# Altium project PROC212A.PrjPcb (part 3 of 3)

## Sheet PROC212A_DCA1000_LP_BP_Connectors.SchDoc: DCA1000_LP_BP_CONN
size 431 x 279 mm; Date: Not shown in title block; ApprovedBy: Not shown in title block; CheckedBy: Not shown in title block; Author: Not shown in title block; CompanyName: Not shown in title block; DrawnBy: Mistral; Engineer: Not shown in title block; Organization: Not shown in title block; Address1: Not shown in title block; Address2: Not shown in title block; Address3: Not shown in title block; Address4: Not shown in title block; DocumentNumber: 14; Revision: Use project parameter SCH_Rev; SheetNumber: 14; SheetTotal: 15; PageSetup: Record=PageOptions¦CenterHorizontal=True¦CenterVertical=True¦PrintScale=1.00¦XCorrection=1.00¦YCorrection=1.00¦PrintKind=0¦BorderSize=5000000¦LeftOffset=0¦BottomOffset=0¦Orientation=2¦PaperLength=1000¦PaperWidth=1000¦Scale=100¦PaperSource=15¦PrintQuality=600¦MediaType=1¦DitherType=10¦PaperKind=Letter¦PrintScaleMode=1
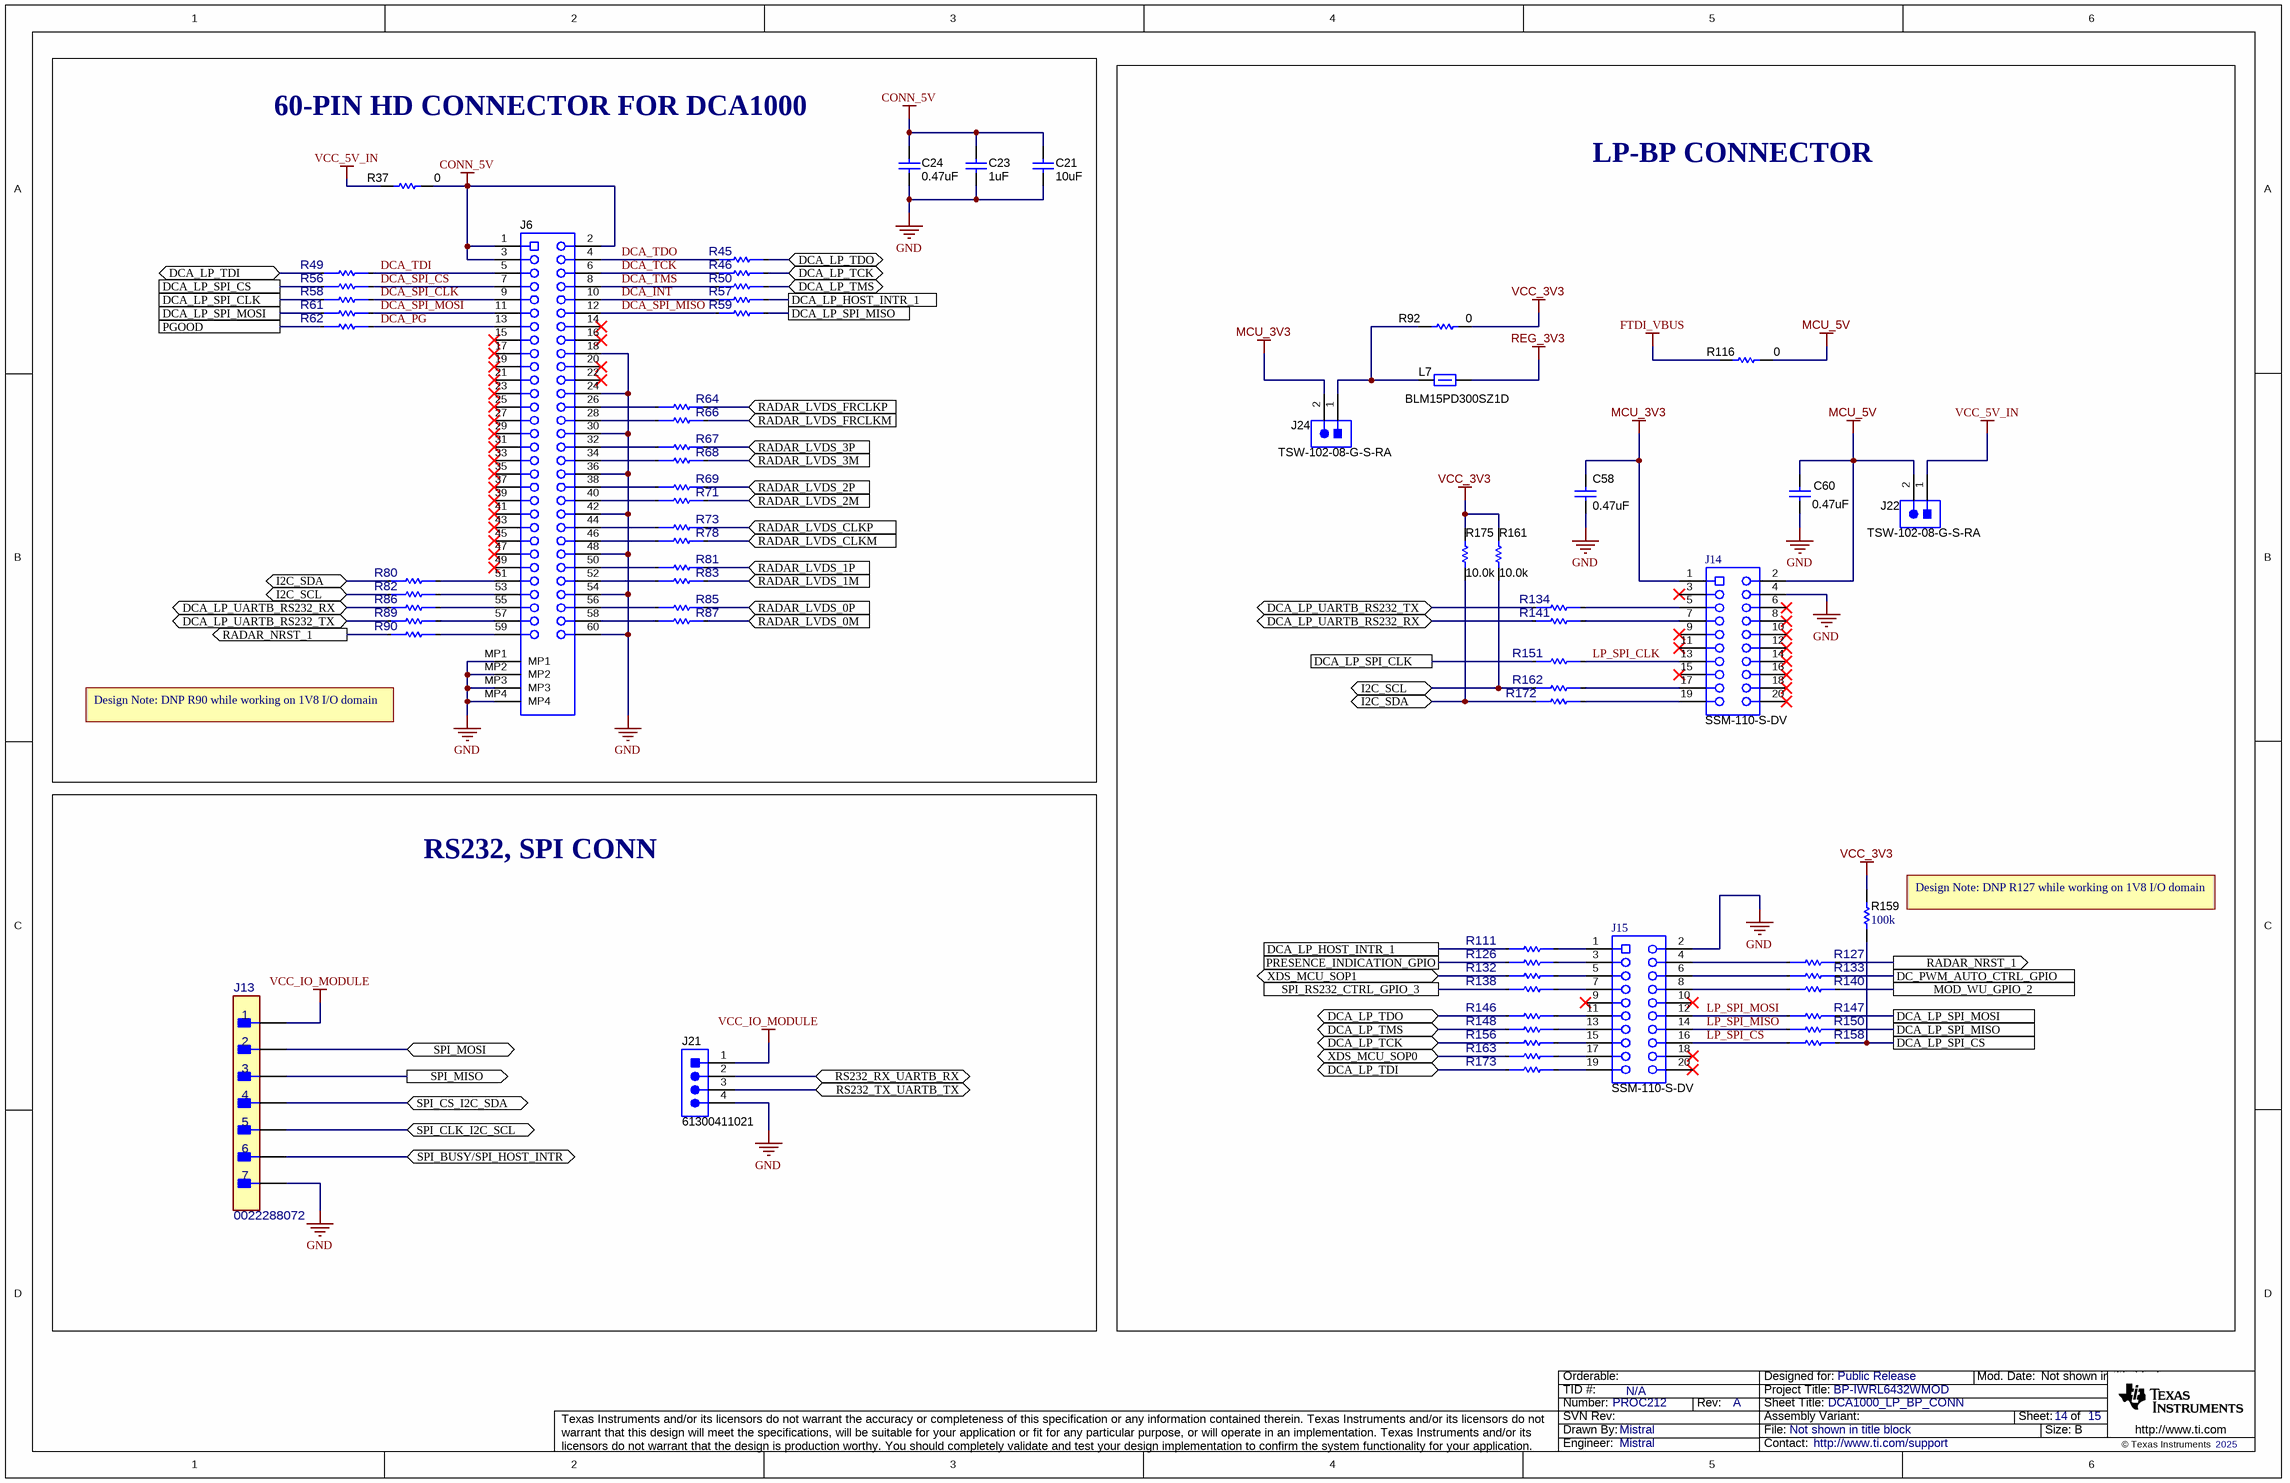
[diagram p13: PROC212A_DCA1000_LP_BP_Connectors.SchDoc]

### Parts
C21  ValueDisplayed: 10uF  [0603S]  (hidden comment: GRT188R61A106KE13D)
C23  ValueDisplayed: 1uF  [0402L]  (hidden comment: GRT155C81A105KE01D)
C24  ValueDisplayed: 0.47uF  [0402L]  (hidden comment: GCM155C71A474KE36D)
C58  ValueDisplayed: 0.47uF  [0402L]  (hidden comment: GCM155C71A474KE36D)
C60  ValueDisplayed: 0.47uF  [0402L]  (hidden comment: GCM155C71A474KE36D)
J6  QSH-030-01-L-D-A  [Samtec_QSH-030-01-X-D-A]  (value not drawn)
J13  0022288072  [FP-0022288072_HDR7-MFG]
J14  SSM-110-S-DV  [Samtec_SSM-110-x-DV]
J15  SSM-110-S-DV  [Samtec_SSM-110-x-DV]
J21  61300411021  [Wurth_61300411021]
J22  TSW-102-08-G-S-RA  [TSW-102-08-G-S-RA]
J24  TSW-102-08-G-S-RA  [TSW-102-08-G-S-RA]
L7  BLM15PD300SZ1D  [0402L]
R37  ValueDisplayed: 0  [0603]  (hidden comment: MCT06030Z0000ZP500)
R45  ERJ-2GE0R00X  [FP-ERJ-2GE0R00X_0402-MFG]  (value not drawn)
R46  ERJ-2GE0R00X  [FP-ERJ-2GE0R00X_0402-MFG]  (value not drawn)
R49  ERJ-2GE0R00X  [FP-ERJ-2GE0R00X_0402-MFG]  (value not drawn)
R50  ERJ-2GE0R00X  [FP-ERJ-2GE0R00X_0402-MFG]  (value not drawn)
R56  ERJ-2GE0R00X  [FP-ERJ-2GE0R00X_0402-MFG]  (value not drawn)
R57  ERJ-2GE0R00X  [FP-ERJ-2GE0R00X_0402-MFG]  (value not drawn)
R58  ERJ-2GE0R00X  [FP-ERJ-2GE0R00X_0402-MFG]  (value not drawn)
R59  ERJ-2GE0R00X  [FP-ERJ-2GE0R00X_0402-MFG]  (value not drawn)
R61  ERJ-2GE0R00X  [FP-ERJ-2GE0R00X_0402-MFG]  (value not drawn)
R62  ERJ-2GE0R00X  [FP-ERJ-2GE0R00X_0402-MFG]  (value not drawn)
R64  ERJ-2GE0R00X  [FP-ERJ-2GE0R00X_0402-MFG]  (value not drawn)
R66  ERJ-2GE0R00X  [FP-ERJ-2GE0R00X_0402-MFG]  (value not drawn)
R67  ERJ-2GE0R00X  [FP-ERJ-2GE0R00X_0402-MFG]  (value not drawn)
R68  ERJ-2GE0R00X  [FP-ERJ-2GE0R00X_0402-MFG]  (value not drawn)
R69  ERJ-2GE0R00X  [FP-ERJ-2GE0R00X_0402-MFG]  (value not drawn)
R71  ERJ-2GE0R00X  [FP-ERJ-2GE0R00X_0402-MFG]  (value not drawn)
R73  ERJ-2GE0R00X  [FP-ERJ-2GE0R00X_0402-MFG]  (value not drawn)
R78  ERJ-2GE0R00X  [FP-ERJ-2GE0R00X_0402-MFG]  (value not drawn)
R80  ERJ-2GE0R00X  [FP-ERJ-2GE0R00X_0402-MFG]  (value not drawn)
R81  ERJ-2GE0R00X  [FP-ERJ-2GE0R00X_0402-MFG]  (value not drawn)
R82  ERJ-2GE0R00X  [FP-ERJ-2GE0R00X_0402-MFG]  (value not drawn)
R83  ERJ-2GE0R00X  [FP-ERJ-2GE0R00X_0402-MFG]  (value not drawn)
R85  ERJ-2GE0R00X  [FP-ERJ-2GE0R00X_0402-MFG]  (value not drawn)
R86  ERJ-2GE0R00X  [FP-ERJ-2GE0R00X_0402-MFG]  (value not drawn)
R87  ERJ-2GE0R00X  [FP-ERJ-2GE0R00X_0402-MFG]  (value not drawn)
R89  ERJ-2GE0R00X  [FP-ERJ-2GE0R00X_0402-MFG]  (value not drawn)
R90  ERJ-2GE0R00X  [FP-ERJ-2GE0R00X_0402-MFG]  (value not drawn)
R92  ValueDisplayed: 0  [0603]  (hidden comment: MCT06030Z0000ZP500)
R111  ERJ-2GE0R00X  [FP-ERJ-2GE0R00X_0402-MFG]  (value not drawn)
R116  ValueDisplayed: 0  [0603]  (hidden comment: MCT06030Z0000ZP500)
R126  ERJ-2GE0R00X  [FP-ERJ-2GE0R00X_0402-MFG]  (value not drawn)
R127  ERJ-2GE0R00X  [FP-ERJ-2GE0R00X_0402-MFG]  (value not drawn)
R132  ERJ-2GE0R00X  [FP-ERJ-2GE0R00X_0402-MFG]  (value not drawn)
R133  ERJ-2GE0R00X  [FP-ERJ-2GE0R00X_0402-MFG]  (value not drawn)
R134  ERJ-2GE0R00X  [FP-ERJ-2GE0R00X_0402-MFG]  (value not drawn)
R138  ERJ-2GE0R00X  [FP-ERJ-2GE0R00X_0402-MFG]  (value not drawn)
R140  ERJ-2GE0R00X  [FP-ERJ-2GE0R00X_0402-MFG]  (value not drawn)
R141  ERJ-2GE0R00X  [FP-ERJ-2GE0R00X_0402-MFG]  (value not drawn)
R146  ERJ-2GE0R00X  [FP-ERJ-2GE0R00X_0402-MFG]  (value not drawn)
R147  ERJ-2GE0R00X  [FP-ERJ-2GE0R00X_0402-MFG]  (value not drawn)
R148  ERJ-2GE0R00X  [FP-ERJ-2GE0R00X_0402-MFG]  (value not drawn)
R150  ERJ-2GE0R00X  [FP-ERJ-2GE0R00X_0402-MFG]  (value not drawn)
R151  ERJ-2GE0R00X  [FP-ERJ-2GE0R00X_0402-MFG]  (value not drawn)
R156  ERJ-2GE0R00X  [FP-ERJ-2GE0R00X_0402-MFG]  (value not drawn)
R158  ERJ-2GE0R00X  [FP-ERJ-2GE0R00X_0402-MFG]  (value not drawn)
R159  ValueDisplayed: 100k  [0402L]  (hidden comment: CRCW0402100KFKED)
R161  ValueDisplayed: 10.0k  [0402L]  (hidden comment: CRCW040210K0FKED)
R162  ERJ-2GE0R00X  [FP-ERJ-2GE0R00X_0402-MFG]  (value not drawn)
R163  ERJ-2GE0R00X  [FP-ERJ-2GE0R00X_0402-MFG]  (value not drawn)
R172  ERJ-2GE0R00X  [FP-ERJ-2GE0R00X_0402-MFG]  (value not drawn)
R173  ERJ-2GE0R00X  [FP-ERJ-2GE0R00X_0402-MFG]  (value not drawn)
R175  ValueDisplayed: 10.0k  [0402L]  (hidden comment: CRCW040210K0FKED)

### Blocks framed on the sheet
60-PIN HD CONNECTOR FOR DCA1000: C21 C23 C24 J6 R37 R45 R46 R49 R50 R56-R59 R61 R62 R64 R66-R69 R71 R73 R78 R80-R83 R85-R87 R89 R90
LP-BP CONNECTOR: C58 C60 J14 J15 J22 J24 L7 R92 R111 R116 R126 R127 R132-R134 R138 R140 R141 R146-R148 R150 R151 R156 R158 R159 R161-R163 R172 R173 R175
RS232, SPI CONN: J13 J21

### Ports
DC_PWM_AUTO_CTRL_GPIO, DCA_LP_HOST_INTR_1, DCA_LP_SPI_CLK, DCA_LP_SPI_CS, DCA_LP_SPI_MISO, DCA_LP_SPI_MOSI, DCA_LP_TCK (bidir), DCA_LP_TDI (bidir), DCA_LP_TDO (bidir), DCA_LP_TMS (bidir), DCA_LP_UARTB_RS232_RX (bidir), DCA_LP_UARTB_RS232_TX (bidir), I2C_SCL (bidir), I2C_SDA (bidir), MOD_WU_GPIO_2, PGOOD, PRESENCE_INDICATION_GPIO, RADAR_LVDS_0M (in), RADAR_LVDS_0P (in), RADAR_LVDS_1M (in), RADAR_LVDS_1P (in), RADAR_LVDS_2M (in), RADAR_LVDS_2P (in), RADAR_LVDS_3M (in), RADAR_LVDS_3P (in), RADAR_LVDS_CLKM (in), RADAR_LVDS_CLKP (in), RADAR_LVDS_FRCLKM (in), RADAR_LVDS_FRCLKP (in), RADAR_NRST_1 (out), RS232_RX_UARTB_RX (bidir), RS232_TX_UARTB_TX (bidir), SPI_BUSY/SPI_HOST_INTR (bidir), SPI_CLK_I2C_SCL (bidir), SPI_CS_I2C_SDA (bidir), SPI_MISO (out), SPI_MOSI (bidir), SPI_RS232_CTRL_GPIO_3, XDS_MCU_SOP0 (bidir), XDS_MCU_SOP1 (bidir)

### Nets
CONN_5V: C21.2 C23.1 C24.1 J6.1 J6.2 J6.3 R37.2
FTDI_VBUS: R116.1
GND: C21.1 C23.2 C24.2 C58.2 C60.2 J6.18 J6.24 J6.30 J6.36 J6.42 J6.48 J6.54 J6.60 J6.MP1 J6.MP2 J6.MP3 J6.MP4 J13.7 J14.4 J15.2 J21.4
MCU_3V3: C58.1 J14.1 J24.2
MCU_5V: C60.1 J14.2 J22.2 R116.2
REG_3V3: L7.2
VCC_3V3: R92.2 R159.2 R161.2 R175.2
VCC_5V_IN: J22.1 R37.1
VCC_IO_MODULE: J13.1 J21.1
DC_PWM_AUTO_CTRL_GPIO: R133.2 ; port DC_PWM_AUTO_CTRL_GPIO
DCA_INT: J6.10 R57.1
DCA_LP_HOST_INTR_1: R57.2 R111.1 ; port DCA_LP_HOST_INTR_1
DCA_LP_SPI_CLK: R58.1 R151.1 ; port DCA_LP_SPI_CLK
DCA_LP_SPI_CS: R56.1 R158.2 R159.1 ; port DCA_LP_SPI_CS
DCA_LP_SPI_MISO: R59.2 R150.2 ; port DCA_LP_SPI_MISO
DCA_LP_SPI_MOSI: R61.1 R147.2 ; port DCA_LP_SPI_MOSI
DCA_LP_TCK: R46.2 R156.1 ; port DCA_LP_TCK
DCA_LP_TDI: R49.1 R173.1 ; port DCA_LP_TDI
DCA_LP_TDO: R45.2 R146.1 ; port DCA_LP_TDO
DCA_LP_TMS: R50.2 R148.1 ; port DCA_LP_TMS
DCA_LP_UARTB_RS232_RX: R86.1 R141.1 ; port DCA_LP_UARTB_RS232_RX
DCA_LP_UARTB_RS232_TX: R89.1 R134.1 ; port DCA_LP_UARTB_RS232_TX
DCA_PG: J6.13 R62.2
DCA_SPI_CLK: J6.9 R58.2
DCA_SPI_CS: J6.7 R56.2
DCA_SPI_MISO: J6.12 R59.1
DCA_SPI_MOSI: J6.11 R61.2
DCA_TCK: J6.6 R46.1
DCA_TDI: J6.5 R49.2
DCA_TDO: J6.4 R45.1
DCA_TMS: J6.8 R50.1
I2C_SCL: R82.1 R161.1 R162.1 ; port I2C_SCL
I2C_SDA: R80.1 R172.1 R175.1 ; port I2C_SDA
LP_SPI_CLK: J14.13 R151.2
LP_SPI_CS: J15.16 R158.1
LP_SPI_MISO: J15.14 R150.1
LP_SPI_MOSI: J15.12 R147.1
MOD_WU_GPIO_2: R140.2 ; port MOD_WU_GPIO_2
PGOOD: R62.1 ; port PGOOD
PRESENCE_INDICATION_GPIO: R126.1 ; port PRESENCE_INDICATION_GPIO
RADAR_LVDS_0M: R87.2 ; port RADAR_LVDS_0M
RADAR_LVDS_0P: R85.2 ; port RADAR_LVDS_0P
RADAR_LVDS_1M: R83.2 ; port RADAR_LVDS_1M
RADAR_LVDS_1P: R81.2 ; port RADAR_LVDS_1P
RADAR_LVDS_2M: R71.2 ; port RADAR_LVDS_2M
RADAR_LVDS_2P: R69.2 ; port RADAR_LVDS_2P
RADAR_LVDS_3M: R68.2 ; port RADAR_LVDS_3M
RADAR_LVDS_3P: R67.2 ; port RADAR_LVDS_3P
RADAR_LVDS_CLKM: R78.2 ; port RADAR_LVDS_CLKM
RADAR_LVDS_CLKP: R73.2 ; port RADAR_LVDS_CLKP
RADAR_LVDS_FRCLKM: R66.2 ; port RADAR_LVDS_FRCLKM
RADAR_LVDS_FRCLKP: R64.2 ; port RADAR_LVDS_FRCLKP
RADAR_NRST_1: R90.1 R127.2 ; port RADAR_NRST_1
RS232_RX_UARTB_RX: J21.2 ; port RS232_RX_UARTB_RX
RS232_TX_UARTB_TX: J21.3 ; port RS232_TX_UARTB_TX
SPI_BUSY/SPI_HOST_INTR: J13.6 ; port SPI_BUSY/SPI_HOST_INTR
SPI_CLK_I2C_SCL: J13.5 ; port SPI_CLK_I2C_SCL
SPI_CS_I2C_SDA: J13.4 ; port SPI_CS_I2C_SDA
SPI_MISO: J13.3 ; port SPI_MISO
SPI_MOSI: J13.2 ; port SPI_MOSI
SPI_RS232_CTRL_GPIO_3: R138.1 ; port SPI_RS232_CTRL_GPIO_3
XDS_MCU_SOP0: R163.1 ; port XDS_MCU_SOP0
XDS_MCU_SOP1: R132.1 ; port XDS_MCU_SOP1
NetJ6_26: J6.26 R64.1
NetJ6_28: J6.28 R66.1
NetJ6_32: J6.32 R67.1
NetJ6_34: J6.34 R68.1
NetJ6_38: J6.38 R69.1
NetJ6_40: J6.40 R71.1
NetJ6_44: J6.44 R73.1
NetJ6_46: J6.46 R78.1
NetJ6_50: J6.50 R81.1
NetJ6_51: J6.51 R80.2
NetJ6_52: J6.52 R83.1
NetJ6_53: J6.53 R82.2
NetJ6_55: J6.55 R86.2
NetJ6_56: J6.56 R85.1
NetJ6_57: J6.57 R89.2
NetJ6_58: J6.58 R87.1
NetJ6_59: J6.59 R90.2
NetJ14_5: J14.5 R134.2
NetJ14_7: J14.7 R141.2
NetJ14_17: J14.17 R162.2
NetJ14_19: J14.19 R172.2
NetJ15_1: J15.1 R111.2
NetJ15_3: J15.3 R126.2
NetJ15_4: J15.4 R127.1
NetJ15_5: J15.5 R132.2
NetJ15_6: J15.6 R133.1
NetJ15_7: J15.7 R138.2
NetJ15_8: J15.8 R140.1
NetJ15_11: J15.11 R146.2
NetJ15_13: J15.13 R148.2
NetJ15_15: J15.15 R156.2
NetJ15_17: J15.17 R163.2
NetJ15_19: J15.19 R173.2
NetJ24_1: J24.1 L7.1 R92.1

Not connected (* = marked no-connect by the designer): J6 14* 15* 16* 17* 19* 20* 21* 22* 23* 25* 27* 29* 31* 33* 35* 37* 39* 41* 43* 45* 47* 49*; J14 3* 6* 8* 9* 10* 11* 12* 14* 15* 16* 18* 20*; J15 9* 10* 18* 20*

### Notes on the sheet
- Design Note: DNP R90 while working on 1V8 I/O domain
- (near R159) Design Note: DNP R127 while working on 1V8 I/O domain

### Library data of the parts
C21 = CMP-0007497-5: CAP, CERM, 10 uF, 10 V, +/- 10%, X5R, 0603; Manufacturer: MuRata; Polarized: N; Value: 10uF; U/M: EA; Cap_F: 10µF; Tolerance_%: 20%; Value1: Unknown; VDC_V: 10V; TempCo: X7R; TaMin_C: -55°C; TaMax_C: 125°C; Cap_Case: 0603; SizeArea_mm2: 1.28; SizeAreaWB_mm2: 4.68; SizeX_mm: 1.6; SizeY_mm: 0.8; SizeZ_mm: 1; AEC Category: Q200
C23 = CMP-0006272-2: CAP, CERM, 1 uF, 10 V, +/- 10%, X6S, 0402; Manufacturer: TDK; Polarized: N; Value: 1uF; U/M: EA; Cap_F: 1µF; Value1: Unknown; VDC_V: 16V; TempCo: X5R; TaMin_C: -55°C; TaMax_C: 85°C; Cap_Case: 0402; SizeArea_mm2: 0.5; SizeAreaWB_mm2: 3; SizeX_mm: 1; SizeZ_mm: 0.6; AEC Category: Q200
C24 C58 C60 = CMP-0064967-2: CAP, CERM, 0.47 uF, 10 V,+/- 10%, X7S, 0402; Manufacturer: MuRata; Polarized: N; Value: 0.47uF; U/M: EA; Cap_F: 470nF; Value1: Unknown; VDC_V: 10V; TaMin_C: -55°C; TaMax_C: 125°C; Cap_Case: 0402; SizeArea_mm2: 0.5; SizeAreaWB_mm2: 3; SizeX_mm: 1; SizeZ_mm: 0.6; AEC Category: Q200
J6 = CMP-0075524-1: Receptacle, 0.5 mm, 30x2, Gold, TH; Manufacturer: Samtec; Pitch_mm: 0.5; Gender: Female; Green_REACh: Passed; CT: False; Shrouded: N; RowSpacing_mm: 5.73; Green_Lifecycle: Active; Row_Count: 2
J13 = CMP-0120118-1: Manufacturer: Molex; ContactFinish: Gold,Nickel; Current_A: 4A; Row_Count: 1; Voltage_V: 600V; AEC Qualified: No; Conn Gender: Male; Conn Orientation: Right Angle; DUT-Pitch_mm: 2.54mm; SizeZ_mm: 2.74mm
J14 J15 = CMP-0078182-1: Receptacle, 2.54mm, 10x2, Gold with Tin tail, SMT; Manufacturer: Samtec; Pitch_mm: 2.54; Gender: Female; Cert_CSA: Y; Voltage_V: 405V; Current_A: 5.2A; Row_Count: 2; CompType: Socket Strip
J21 = CMP-0054797-1: Header, 2.54 mm, 4x1, Gold, R/A, TH; Manufacturer: Wurth Elektronik; CNHeader: TRUE; Shrouded: N; Gender: Male; Row_Count: 1; Pitch_mm: 2.54; CT: FALSE
J22 J24 = CMP-0055976-1: Header, 100mil, 2x1, Gold, R/A, TH; Manufacturer: Samtec; Cert_VDE: N; CNHeader: FALSE; Current_A: 6.3A; Green_Lifecycle: Active; Gender: Male; Cert_CSA: Y; Green_REACh: Passed; Voltage_V: 550V; Row_Count: 1; Pitch_mm: 2.54
L7 = CMP-0078934-1: Inductor, Ferrite Bead, Ferrite, 2.2 A, 0.035 ohm, AEC-Q200 Grade 1, SMD; Manufacturer: MuRata; AEC Category: Q200; AEC Grade: 1; AEC Qualified: Y; DCR_ohm: 0.035; Imax_A: 2.2A; SizeArea_mm2: 0.5; SizeAreaWB_mm2: 3; SizeZ_mm: 0.6
R37 R92 R116 = CMP-0025884-3: RES, 0, 5%, 0.125 W, 0603; Manufacturer: Vishay/Beyschlag; Power_W: 125mW; TempCo: ppm/C; Value_Code: 0000; U/M: EA; Value: 0; EIA_Code: E24; SizeX_mm: 1.6; SizeY_mm: 0.8; SizeZ_mm: 1; Value2: 0.125W; SizeArea_mm2: 1.28; CompType: Resistor; AEC Qualified: N; AEC Category: Q200; INSTALATION: DNP
R45 R46 R49 R50 R56-R59 R61 R62 R64 R66-R69 R71 R73 R78 R80-R83 R85-R87 R89 R90 R111 R126 R127 R132-R134 R138 R140 R141 R146-R148 R150 R151 R156 R158 R162 R163 R172 R173 = CMP-0002710-1: 0 Ohms Jumper Chip Resistor 0402 (1005 Metric) Automotive AEC-Q200 Thick Film; Manufacturer: Panasonic; Value: 0; SizeZ_mm: 0.4mm; AEC Qualified: Yes; AEC Grade: Grade 0; Power: 100mW
R159 = CMP-0025950-3: RES, 100 k, 1%, 0.063 W, AEC-Q200 Grade 0, 0402; Manufacturer: Vishay-Dale; Power_W: 63mW; TempCo: 100 ppm/C; Value: 100k; EIA_Code: E96; SizeX_mm: 1; SizeY_mm: 0.5; SizeZ_mm: 0.6; Value2: 0.063W; AEC Qualified: Y; VDC_V: 50V; AEC Category: Q200; AEC Grade: 0
R161 R175 = CMP-0025958-3: RES, 10.0 k, 1%, 0.063 W, AEC-Q200 Grade 0, 0402; Manufacturer: Vishay-Dale; Power_W: 63mW; TempCo: 100 ppm/C; Value_Code: 10k0; Value: 10.0k; EIA_Code: E96; Res_ohm: 10k; SizeX_mm: 1; SizeY_mm: 0.5; SizeZ_mm: 0.6; Value2: 0.063W; AEC Qualified: Y; VDC_V: 50V; AEC Category: Q200; AEC Grade: 0

## Sheet PROC212A_EVM_Hardware.SchDoc: HARDWARE
size 431 x 279 mm; Date: Not shown in title block; ApprovedBy: Not shown in title block; CheckedBy: Not shown in title block; Author: Not shown in title block; CompanyName: Not shown in title block; DrawnBy: Mistral; Engineer: Not shown in title block; Organization: Not shown in title block; Address1: Not shown in title block; Address2: Not shown in title block; Address3: Not shown in title block; Address4: Not shown in title block; DocumentNumber: 15; Revision: Use project parameter SCH_Rev; SheetNumber: 15; SheetTotal: 15; PageSetup: Record=PageOptions¦CenterHorizontal=True¦CenterVertical=True¦PrintScale=1.00¦XCorrection=1.00¦YCorrection=1.00¦PrintKind=0¦BorderSize=5000000¦LeftOffset=0¦BottomOffset=0¦Orientation=2¦PaperLength=1000¦PaperWidth=1000¦Scale=100¦PaperSource=15¦PrintQuality=600¦MediaType=1¦DitherType=10¦PaperKind=Letter¦PrintScaleMode=1
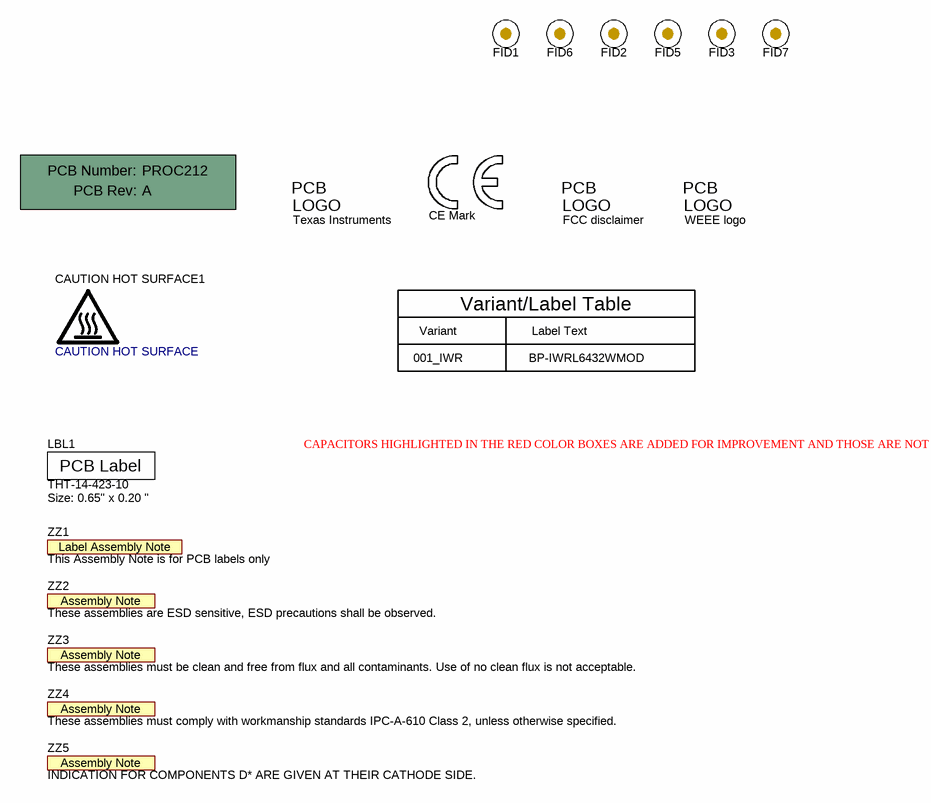
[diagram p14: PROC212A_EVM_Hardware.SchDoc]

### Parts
!PCB  Printed Circuit Board  (value not drawn)  (mechanical)
CAUTION_HOT_SURFACE1  CAUTION HOT SURFACE  [IEC_HotSurface_Small]  (no BOM)
FID1  Fiducial  [Fiducial10-20]  (value not drawn)
FID2  Fiducial  [Fiducial10-20]  (value not drawn)
FID3  Fiducial  [Fiducial10-20]  (value not drawn)
FID5  Fiducial  [Fiducial10-20]  (value not drawn)
FID6  Fiducial  [Fiducial10-20]  (value not drawn)
FID7  Fiducial  [Fiducial10-20]  (value not drawn)
LBL1  THT-14-423-10  Note: Size: 0.65" x 0.20 "  [Label_650x200]
Logo1  Texas Instruments  [TI_Stacked_Overlay_Small]  (no BOM)
Logo2  WEEE logo  [WEEE_Minimum]  (no BOM)
Logo3  FCC disclaimer  [FCC_disclaimer]  (no BOM)
Logo4  CE Mark  [CE_Mark_5mm]  (no BOM)
ZZ1  This Assembly Note is for PCB labels only  [AssemblyNoteLabel]  (no BOM)
ZZ2  These assemblies are ESD sensitive, ESD precautions shall be observed.  [AssemblyNote]  (no BOM)
ZZ3  These assemblies must be clean and free from flux and all contaminants. Use of no clean flux is not acceptable.  [AssemblyNote]  (no BOM)
ZZ4  These assemblies must comply with workmanship standards IPC-A-610 Class 2, unless otherwise specified.  [AssemblyNote]  (no BOM)
ZZ5  INDICATION FOR COMPONENTS D* ARE GIVEN AT THEIR CATHODE SIDE.  [AssemblyNote]  (no BOM)

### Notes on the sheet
- Variant
- 001_IWR
- Variant/Label Table
- Label Text
- BP-IWRL6432WMOD
- CAPACITORS HIGHLIGHTED IN THE RED COLOR BOXES ARE ADDED FOR IMPROVEMENT AND THOSE ARE NOT MANDITORY.

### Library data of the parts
!PCB = CMP-0003618-2: Manufacturer: Any; PartNumber: PROC212
CAUTION_HOT_SURFACE1 = CMP-0074837-2: IEC 61010-1 Hot Surface Warning; Manufacturer: Texas Instruments; SymbolCreator: a0412235; AEC Category: Q200; CompType: IC
FID1-FID3 FID5-FID7 = CMP-0077181-1: Fiducial mark.  There is nothing to buy or mount.
LBL1 = CMP-0003625-1: Thermal Transfer Printable Labels, 0.650" W x 0.200" H - 10,000 per roll; Manufacturer: Brady; CompType: Label
Logo1 = CMP-0074838-1: Texas Instrument Corporate Signature; SymbolCreator: a0412235; Lib Reference: TI_Logo; Library Reference: Logo
Logo2 = CMP-0074769-1
Logo3 = CMP-0074847-1: FCC_disclaimer; Library Reference: Logo
Logo4 = CMP-0074844-1: SymbolCreator: a0412235
ZZ1 = CMP-0003616-3
ZZ2 = CMP-0077236-1
ZZ3 = CMP-0077237-1
ZZ4 ZZ5 = CMP-0077238-1

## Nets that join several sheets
5V_IN_USB: PROC212A_USB_DC_JACK_PWR_Switch (11 pins), PROC212A_DC_Regulators (R214.2)
FTDI_VBUS: PROC212A_USB_DC_JACK_PWR_Switch (L1.1), PROC212A_FTDI (C22.2 J5.1 R185.2), PROC212A_DCA1000_LP_BP_Connectors (R116.1)
GND: PROC212A_BP_MMWAVE_MODULE (10 pins), PROC212A_USB_DC_JACK_PWR_Switch (31 pins), PROC212A_DC_Regulators (33 pins), PROC212A_ANALOG_MUX_LVDS_DRIVER (15 pins), PROC212A_ANALOG_MUX_SPI (11 pins), PROC212A_ANALOG_JTAG_MUX, CAN & SOP_CTRL (17 pins), PROC212A_Current_sensors_EPROM (16 pins), PROC212A_XDS110_Interface (33 pins), PROC212A_FTDI (42 pins), PROC212A_Reset_SW_LED_&_PRESENCE_LED (7 pins), PROC212A_DCA1000_LP_BP_Connectors (21 pins)
REG_3V3: PROC212A_DC_Regulators (C56.2 L6.2 R75.2), PROC212A_ANALOG_JTAG_MUX, CAN & SOP_CTRL (R20.2), PROC212A_Current_sensors_EPROM (6 pins), PROC212A_DCA1000_LP_BP_Connectors (L7.2)
VCC_1V8: PROC212A_BP_MMWAVE_MODULE (J2.1 J3.1 J17.2 J18.1), PROC212A_DC_Regulators (R18.2)
VCC_3V3: PROC212A_DC_Regulators (5 pins), PROC212A_ANALOG_MUX_LVDS_DRIVER (7 pins), PROC212A_ANALOG_MUX_SPI (12 pins), PROC212A_ANALOG_JTAG_MUX, CAN & SOP_CTRL (6 pins), PROC212A_Current_sensors_EPROM (21 pins), PROC212A_FTDI (L9.1 R36.2), PROC212A_Reset_SW_LED_&_PRESENCE_LED (R107.2 R128.2), PROC212A_DCA1000_LP_BP_Connectors (R92.2 R159.2 R161.2 R175.2)
VCC_5V: PROC212A_USB_DC_JACK_PWR_Switch (R88.2 R93.2), PROC212A_DC_Regulators (16 pins), PROC212A_Current_sensors_EPROM (J9.2 R91.2)
VCC_5V_IN: PROC212A_USB_DC_JACK_PWR_Switch (6 pins), PROC212A_Current_sensors_EPROM (R192.1 U23.8 U23.10), PROC212A_DCA1000_LP_BP_Connectors (J22.1 R37.1)
VCC_IO_3V3: PROC212A_BP_MMWAVE_MODULE (J4.1 J20.2), PROC212A_Current_sensors_EPROM (J10.2 R94.2)
VCC_IO_MODULE: PROC212A_BP_MMWAVE_MODULE (6 pins), PROC212A_ANALOG_MUX_LVDS_DRIVER (R14.2 R181.2), PROC212A_ANALOG_JTAG_MUX, CAN & SOP_CTRL (R165.2 S1.16), PROC212A_Reset_SW_LED_&_PRESENCE_LED (5 pins), PROC212A_DCA1000_LP_BP_Connectors (J13.1 J21.1)
VCC_MOD_3V3: PROC212A_BP_MMWAVE_MODULE (J1.1 J16.1), PROC212A_Current_sensors_EPROM (J11.2 R95.2)
VCC_XDS_3V3: PROC212A_DC_Regulators (R145.2), PROC212A_XDS110_Interface (28 pins)
VPP_1P7: PROC212A_BP_MMWAVE_MODULE (U1.23), PROC212A_DC_Regulators (C4.2 U4.5)
XDSET_1_VBUS: PROC212A_USB_DC_JACK_PWR_Switch (R60.1 U14.6), PROC212A_XDS110_Interface (R153.2 R166.2)
CAN_FD_RX: PROC212A_ANALOG_MUX_SPI (U21.19), PROC212A_ANALOG_JTAG_MUX, CAN & SOP_CTRL (R15.2)
CAN_FD_RX_SPI_RS232_CTRL_GPIO_3: PROC212A_ANALOG_MUX_LVDS_DRIVER (U6.22), PROC212A_ANALOG_MUX_SPI (U21.9)
CAN_FD_TX: PROC212A_ANALOG_MUX_LVDS_DRIVER (U6.20), PROC212A_ANALOG_JTAG_MUX, CAN & SOP_CTRL (R155.2)
DC_PWM_AUTO_CTRL_GPIO: PROC212A_ANALOG_MUX_LVDS_DRIVER (U6.16), PROC212A_FTDI (R40.2), PROC212A_DCA1000_LP_BP_Connectors (R133.2)
DCA_LP_HOST_INTR_1: PROC212A_ANALOG_MUX_SPI (U21.16), PROC212A_DCA1000_LP_BP_Connectors (R57.2 R111.1)
DCA_LP_SPI_CLK: PROC212A_ANALOG_MUX_SPI (U21.23), PROC212A_DCA1000_LP_BP_Connectors (R58.1 R151.1)
DCA_LP_SPI_CS: PROC212A_ANALOG_MUX_SPI (U21.22), PROC212A_DCA1000_LP_BP_Connectors (R56.1 R158.2 R159.1)
DCA_LP_SPI_MISO: PROC212A_ANALOG_MUX_SPI (U21.20), PROC212A_DCA1000_LP_BP_Connectors (R59.2 R150.2)
DCA_LP_SPI_MOSI: PROC212A_ANALOG_MUX_SPI (U21.18), PROC212A_DCA1000_LP_BP_Connectors (R61.1 R147.2)
DCA_LP_TCK: PROC212A_ANALOG_JTAG_MUX, CAN & SOP_CTRL (U17.2), PROC212A_DCA1000_LP_BP_Connectors (R46.2 R156.1)
DCA_LP_TDI: PROC212A_ANALOG_JTAG_MUX, CAN & SOP_CTRL (U17.5), PROC212A_DCA1000_LP_BP_Connectors (R49.1 R173.1)
DCA_LP_TDO: PROC212A_ANALOG_JTAG_MUX, CAN & SOP_CTRL (U17.11), PROC212A_DCA1000_LP_BP_Connectors (R45.2 R146.1)
DCA_LP_TMS: PROC212A_ANALOG_JTAG_MUX, CAN & SOP_CTRL (U17.14), PROC212A_DCA1000_LP_BP_Connectors (R50.2 R148.1)
DCA_LP_UARTB_RS232_RX: PROC212A_ANALOG_MUX_SPI (U19.7), PROC212A_DCA1000_LP_BP_Connectors (R86.1 R141.1)
DCA_LP_UARTB_RS232_TX: PROC212A_ANALOG_MUX_SPI (U19.9), PROC212A_DCA1000_LP_BP_Connectors (R89.1 R134.1)
FTDI_HOST_INTR_1: PROC212A_ANALOG_MUX_SPI (U21.15), PROC212A_FTDI (R47.2 R51.2)
FTDI_SOP0: PROC212A_ANALOG_JTAG_MUX, CAN & SOP_CTRL (R32.1), PROC212A_FTDI (R26.2)
FTDI_SOP1: PROC212A_ANALOG_JTAG_MUX, CAN & SOP_CTRL (R98.1), PROC212A_FTDI (R27.2)
FTDI_SPI_CLK: PROC212A_ANALOG_MUX_SPI (U21.8), PROC212A_FTDI (R190.2)
FTDI_SPI_CS: PROC212A_ANALOG_MUX_SPI (U21.10), PROC212A_FTDI (R36.1 R41.2)
FTDI_SPI_MISO: PROC212A_ANALOG_MUX_SPI (U21.12), PROC212A_FTDI (R44.2)
FTDI_SPI_MOSI: PROC212A_ANALOG_MUX_SPI (U21.14), PROC212A_FTDI (R48.2)
FTDI_UARTB_RS232_RX: PROC212A_ANALOG_MUX_SPI (U19.4), PROC212A_FTDI (R178.2)
FTDI_UARTB_RS232_TX: PROC212A_ANALOG_MUX_SPI (U19.2), PROC212A_FTDI (R170.2)
I2C_SCL: PROC212A_ANALOG_MUX_SPI (U20.2), PROC212A_Current_sensors_EPROM (R198.2 R209.2 R218.2), PROC212A_XDS110_Interface (R186.1 S3.2), PROC212A_FTDI (R55.2), PROC212A_DCA1000_LP_BP_Connectors (R82.1 R161.1 R162.1)
I2C_SDA: PROC212A_ANALOG_MUX_SPI (U20.4), PROC212A_Current_sensors_EPROM (R197.2 R204.2 R222.2), PROC212A_XDS110_Interface (R184.1 S3.1), PROC212A_FTDI (R53.2 R54.2), PROC212A_DCA1000_LP_BP_Connectors (R80.1 R172.1 R175.1)
LVDS_CLK_DC_PWM_AUTO_CTRL_GPIO: PROC212A_BP_MMWAVE_MODULE (U1.14), PROC212A_ANALOG_MUX_LVDS_DRIVER (U6.7)
LVDS_D0_MODULE_WAKEUP_GPIO_2: PROC212A_BP_MMWAVE_MODULE (U1.3), PROC212A_ANALOG_MUX_LVDS_DRIVER (U6.1)
LVDS_D1_CAN_FD_RX_SPI_RS232_CTRL_GPIO_3: PROC212A_BP_MMWAVE_MODULE (U1.9), PROC212A_ANALOG_MUX_LVDS_DRIVER (U6.3)
LVDS_D2_CAN_FD_TX: PROC212A_BP_MMWAVE_MODULE (U1.22), PROC212A_ANALOG_MUX_LVDS_DRIVER (U6.4)
LVDS_D3_PRESENCE_INDICATION_GPIO: PROC212A_BP_MMWAVE_MODULE (U1.2), PROC212A_ANALOG_MUX_LVDS_DRIVER (U6.6)
LVDS_FRCLK_HOST_CLK_REQ: PROC212A_BP_MMWAVE_MODULE (U1.24), PROC212A_ANALOG_MUX_LVDS_DRIVER (U6.9)
MOD_WU_GPIO_2: PROC212A_ANALOG_MUX_LVDS_DRIVER (R14.1 R19.2 U6.23), PROC212A_FTDI (R42.2), PROC212A_DCA1000_LP_BP_Connectors (R140.2)
MUX_CTRL_FTDI_DCA_LP_XDS_RS232: PROC212A_ANALOG_MUX_SPI (R105.1 U16.1 U16.5), PROC212A_ANALOG_JTAG_MUX, CAN & SOP_CTRL (S1.5)
MUX_CTRL_FTDI_DCA_RS232: PROC212A_ANALOG_MUX_SPI (R144.1 U19.1 U19.5), PROC212A_ANALOG_JTAG_MUX, CAN & SOP_CTRL (S1.7)
MUX_CTRL_FTDI_DCA_SPI: PROC212A_ANALOG_MUX_SPI (R177.2 U21.11 U21.21), PROC212A_ANALOG_JTAG_MUX, CAN & SOP_CTRL (S1.6)
MUX_CTRL_LVDS_CAN_GPIO_TP: PROC212A_ANALOG_MUX_LVDS_DRIVER (R23.2 U6.11 U6.21), PROC212A_ANALOG_JTAG_MUX, CAN & SOP_CTRL (S1.2)
MUX_CTRL_SPI_I2C: PROC212A_ANALOG_MUX_SPI (R149.1 U20.1 U20.5), PROC212A_ANALOG_JTAG_MUX, CAN & SOP_CTRL (S1.3)
NRESET: PROC212A_BP_MMWAVE_MODULE (U1.15), PROC212A_DC_Regulators (R74.2), PROC212A_Reset_SW_LED_&_PRESENCE_LED (R96.2 U2.4)
PGOOD: PROC212A_USB_DC_JACK_PWR_Switch (R203.1), PROC212A_DC_Regulators (R16.1 R201.2 R202.1), PROC212A_DCA1000_LP_BP_Connectors (R62.1)
PMIC_CLK_OUT_SOP1: PROC212A_BP_MMWAVE_MODULE (U1.4), PROC212A_ANALOG_JTAG_MUX, CAN & SOP_CTRL (R102.1 R106.1)
PRESENCE_INDICATION_GPIO: PROC212A_ANALOG_MUX_LVDS_DRIVER (U6.18), PROC212A_FTDI (R39.2), PROC212A_Reset_SW_LED_&_PRESENCE_LED (R109.2), PROC212A_DCA1000_LP_BP_Connectors (R126.1)
RADAR_LVDS_0M: PROC212A_ANALOG_MUX_LVDS_DRIVER (U11.11), PROC212A_DCA1000_LP_BP_Connectors (R87.2)
RADAR_LVDS_0P: PROC212A_ANALOG_MUX_LVDS_DRIVER (U11.10), PROC212A_DCA1000_LP_BP_Connectors (R85.2)
RADAR_LVDS_1M: PROC212A_ANALOG_MUX_LVDS_DRIVER (U11.13), PROC212A_DCA1000_LP_BP_Connectors (R83.2)
RADAR_LVDS_1P: PROC212A_ANALOG_MUX_LVDS_DRIVER (U11.14), PROC212A_DCA1000_LP_BP_Connectors (R81.2)
RADAR_LVDS_2M: PROC212A_ANALOG_MUX_LVDS_DRIVER (U9.5), PROC212A_DCA1000_LP_BP_Connectors (R71.2)
RADAR_LVDS_2P: PROC212A_ANALOG_MUX_LVDS_DRIVER (U9.6), PROC212A_DCA1000_LP_BP_Connectors (R69.2)
RADAR_LVDS_3M: PROC212A_ANALOG_MUX_LVDS_DRIVER (U9.3), PROC212A_DCA1000_LP_BP_Connectors (R68.2)
RADAR_LVDS_3P: PROC212A_ANALOG_MUX_LVDS_DRIVER (U9.2), PROC212A_DCA1000_LP_BP_Connectors (R67.2)
RADAR_LVDS_CLKM: PROC212A_ANALOG_MUX_LVDS_DRIVER (U11.5), PROC212A_DCA1000_LP_BP_Connectors (R78.2)
RADAR_LVDS_CLKP: PROC212A_ANALOG_MUX_LVDS_DRIVER (U11.6), PROC212A_DCA1000_LP_BP_Connectors (R73.2)
RADAR_LVDS_FRCLKM: PROC212A_ANALOG_MUX_LVDS_DRIVER (U9.13), PROC212A_DCA1000_LP_BP_Connectors (R66.2)
RADAR_LVDS_FRCLKP: PROC212A_ANALOG_MUX_LVDS_DRIVER (U9.14), PROC212A_DCA1000_LP_BP_Connectors (R64.2)
RADAR_NRST_1: PROC212A_Reset_SW_LED_&_PRESENCE_LED (R2.1 U2.1), PROC212A_DCA1000_LP_BP_Connectors (R90.1 R127.2)
RADAR_NRST_2: PROC212A_FTDI (R180.2), PROC212A_Reset_SW_LED_&_PRESENCE_LED (5 pins)
RS232_RX_UARTB_RX: PROC212A_BP_MMWAVE_MODULE (U1.12), PROC212A_ANALOG_MUX_SPI (R97.2), PROC212A_DCA1000_LP_BP_Connectors (J21.2)
RS232_TX_UARTB_TX: PROC212A_BP_MMWAVE_MODULE (U1.13), PROC212A_ANALOG_MUX_SPI (R110.2), PROC212A_DCA1000_LP_BP_Connectors (J21.3)
SPI_BUSY/SPI_HOST_INTR: PROC212A_BP_MMWAVE_MODULE (U1.1), PROC212A_ANALOG_MUX_SPI (R174.2), PROC212A_DCA1000_LP_BP_Connectors (J13.6)
SPI_CLK_I2C_SCL: PROC212A_BP_MMWAVE_MODULE (U1.20), PROC212A_ANALOG_MUX_SPI (R164.2), PROC212A_DCA1000_LP_BP_Connectors (J13.5)
SPI_CS_I2C_SDA: PROC212A_BP_MMWAVE_MODULE (U1.19), PROC212A_ANALOG_MUX_SPI (R171.2), PROC212A_DCA1000_LP_BP_Connectors (J13.4)
SPI_MISO: PROC212A_BP_MMWAVE_MODULE (U1.18), PROC212A_ANALOG_MUX_SPI (R168.2), PROC212A_DCA1000_LP_BP_Connectors (J13.3)
SPI_MOSI: PROC212A_BP_MMWAVE_MODULE (U1.21), PROC212A_ANALOG_MUX_SPI (R169.2), PROC212A_DCA1000_LP_BP_Connectors (J13.2)
SPI_RS232_CTRL_GPIO_3: PROC212A_ANALOG_MUX_LVDS_DRIVER (R179.2 R181.1), PROC212A_ANALOG_MUX_SPI (U21.13), PROC212A_FTDI (R52.2), PROC212A_DCA1000_LP_BP_Connectors (R138.1)
TCK: PROC212A_BP_MMWAVE_MODULE (U1.17), PROC212A_ANALOG_JTAG_MUX, CAN & SOP_CTRL (R104.2)
TDI: PROC212A_BP_MMWAVE_MODULE (U1.16), PROC212A_ANALOG_JTAG_MUX, CAN & SOP_CTRL (R103.2)
TDO_SOP0: PROC212A_BP_MMWAVE_MODULE (U1.10), PROC212A_ANALOG_JTAG_MUX, CAN & SOP_CTRL (R29.1 R130.2)
TMS: PROC212A_BP_MMWAVE_MODULE (U1.11), PROC212A_ANALOG_JTAG_MUX, CAN & SOP_CTRL (R129.2)
XDS_MCU_SOP0: PROC212A_ANALOG_JTAG_MUX, CAN & SOP_CTRL (R31.1 R32.2), PROC212A_XDS110_Interface (R118.1), PROC212A_DCA1000_LP_BP_Connectors (R163.1)
XDS_MCU_SOP1: PROC212A_ANALOG_JTAG_MUX, CAN & SOP_CTRL (R98.2 R100.1), PROC212A_XDS110_Interface (R117.1), PROC212A_DCA1000_LP_BP_Connectors (R132.1)
XDS_NRST: PROC212A_XDS110_Interface (R112.2), PROC212A_Reset_SW_LED_&_PRESENCE_LED (R1.1 U2.3)
XDS_SCL: PROC212A_Current_sensors_EPROM (R6.2 R12.2), PROC212A_XDS110_Interface (R186.2 S3.3 U18.112)
XDS_SDA: PROC212A_Current_sensors_EPROM (R7.2 R11.2), PROC212A_XDS110_Interface (R184.2 S3.4 U18.111)
XDS_TCK: PROC212A_ANALOG_JTAG_MUX, CAN & SOP_CTRL (U17.3), PROC212A_XDS110_Interface (R115.2)
XDS_TDI: PROC212A_ANALOG_JTAG_MUX, CAN & SOP_CTRL (U17.6), PROC212A_XDS110_Interface (R113.2)
XDS_TDO: PROC212A_ANALOG_JTAG_MUX, CAN & SOP_CTRL (U17.10), PROC212A_XDS110_Interface (U18.37)
XDS_TMS: PROC212A_ANALOG_JTAG_MUX, CAN & SOP_CTRL (U17.13), PROC212A_XDS110_Interface (R114.2)
XDS_UARTB_RS232_RX: PROC212A_ANALOG_MUX_SPI (U16.4), PROC212A_XDS110_Interface (R124.2)
XDS_UARTB_RS232_TX: PROC212A_ANALOG_MUX_SPI (U16.2), PROC212A_XDS110_Interface (R125.2)
XDSET_1_DM: PROC212A_USB_DC_JACK_PWR_Switch (J7.2 U14.4), PROC212A_XDS110_Interface (U18.93)
XDSET_1_DP: PROC212A_USB_DC_JACK_PWR_Switch (J7.3 U14.5), PROC212A_XDS110_Interface (U18.94)
XDSET_1_ID: PROC212A_USB_DC_JACK_PWR_Switch (J7.4 U14.2), PROC212A_XDS110_Interface (R160.1)

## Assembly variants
001_IWR: not fitted C33 C55 C88 C94 FB2 FID1 FID2 FID3 FID5 FID6 FID7 J2 J3 J9 J10 J11 L7 R4 R8 R17 R19 R26 R27 R32 R37 R47 R74 R84 R98 R116 R157 R170 R178 R179 R180 R184 R186 R194 R195 R199 R201 R207 R211 R212 R217 R219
